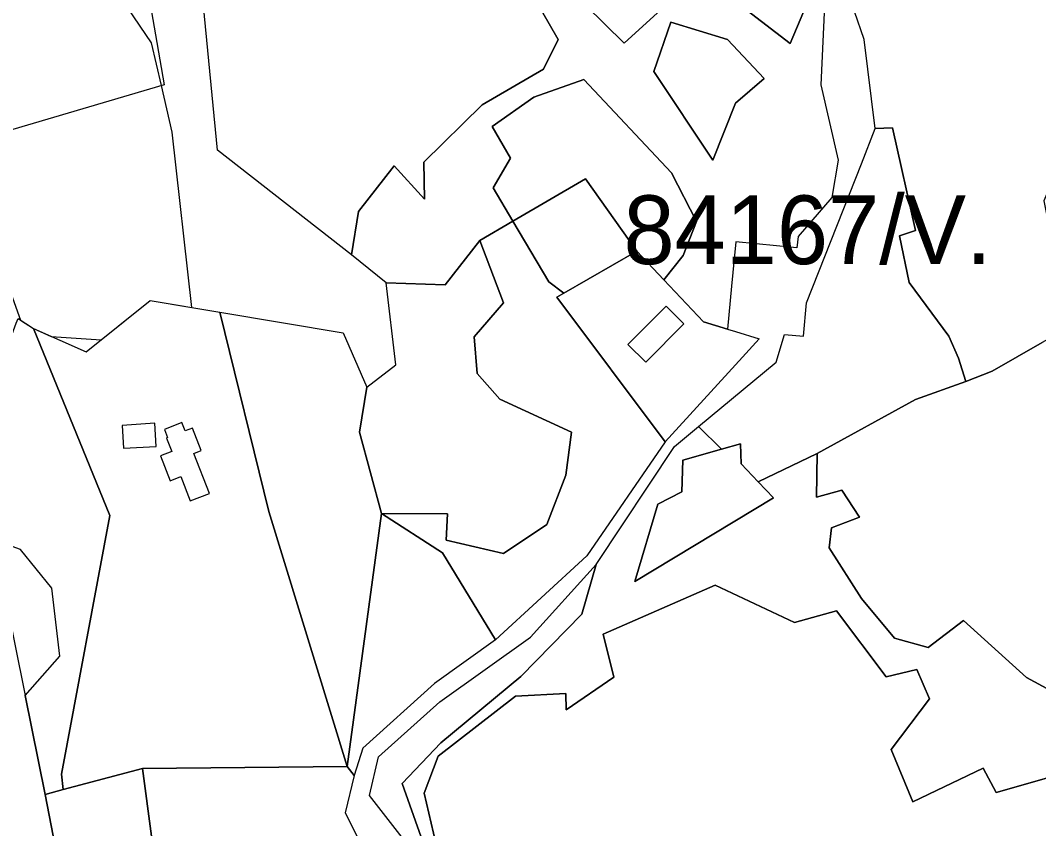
# Model space of a CAD drawing. Extents: x -477304 to -465429, y -1159113 to -1149210.
# Drawn here: x -475087.6 to -474865.5, y -1151412.5 to -1151236.1 of the extents above; entities that cross this region are included whole.
import ezdxf

# ---------------------------------------------------------------- set-up
doc = ezdxf.new("R2010")
doc.units = 0
for name, color, linetype in [('BPEJ_s', 7, 'Continuous'), ('orna_s', 7, 'Continuous'), ('PUPFL_s', 7, 'Continuous'), ('trav_porost_s', 7, 'Continuous'), ('zahrada_s', 7, 'Continuous')]:
    doc.layers.add(name, color=color, linetype=linetype)

msp = doc.modelspace()

# ---------------------------------------------------------------- linework, layer by layer
at = {"layer": 'BPEJ_s'}
msp.add_lwpolyline([(-475097.5, -1151274.05), (-475087.6, -1151301.52), (-475084.79, -1151303.35), (-475080.93, -1151305.06), (-475076.58, -1151305.36), (-475070.02, -1151305.82), (-475059.29, -1151297.19), (-475050.25, -1151298.71), (-475054.5, -1151260.5), (-475056.85, -1151250.3), (-475059, -1151241), (-475088.5, -1151197.5)], dxfattribs=at)
msp.add_lwpolyline([(-475097.5, -1151274.05), (-475087.6, -1151301.52), (-475084.79, -1151303.35), (-475080.93, -1151305.06), (-475076.58, -1151305.36), (-475070.02, -1151305.82), (-475059.29, -1151297.19), (-475050.25, -1151298.71), (-475054.5, -1151260.5), (-475056.85, -1151250.3), (-475059, -1151241), (-475088.5, -1151197.5)], dxfattribs=at)
at = {"layer": 'orna_s'}
for points in [[(-475073.3, -1151308.45), (-475059.29, -1151297.19), (-475044.09, -1151299.75), (-475033.4, -1151343.25), (-475016.37, -1151398.97), (-475060.99, -1151399.35), (-475078.27, -1151403.96), (-475078.67, -1151400.58), (-475068.11, -1151344.11), (-475084.79, -1151303.35)], [(-475065.43, -1151324.48), (-475065.15, -1151329.47), (-475058.04, -1151329.07), (-475058.32, -1151323.98)], [(-475048.2, -1151329.99), (-475050.1, -1151325.06), (-475051.69, -1151325.67), (-475052.38, -1151323.87), (-475056.21, -1151325.35), (-475055.51, -1151327.15), (-475055.74, -1151327.24), (-475054.61, -1151330.17), (-475057.04, -1151331.11), (-475054.94, -1151336.55), (-475052.63, -1151335.66), (-475050.59, -1151340.95), (-475046.41, -1151339.34), (-475049.78, -1151330.6)], [(-475060.99, -1151399.35), (-475057.18, -1151427.79), (-475077.46, -1151429.88), (-475082.26, -1151405.02), (-475078.27, -1151403.96)]]:
    msp.add_lwpolyline(points, close=True, dxfattribs=at)
at = {"layer": 'PUPFL_s'}
msp.add_lwpolyline([(-475060.36, -1151226.55), (-475056.29, -1151250.13), (-475098.2, -1151262.5)], dxfattribs=at)
at = {"layer": 'trav_porost_s'}
for points in [[(-475047.71, -1151232.87), (-475050.28, -1151227.84), (-475056.07, -1151224.83), (-475054.41, -1151208.13), (-475050, -1151194.33), (-475037.4, -1151193.53), (-475018.48, -1151195.89), (-474998.6, -1151206.44), (-474978.98, -1151225.14), (-474970.27, -1151240.23), (-474973.53, -1151246.68), (-474986.86, -1151254.47), (-474999.59, -1151267), (-474999.46, -1151275.08), (-475006.05, -1151267.82), (-475013.84, -1151277.82), (-475015.4, -1151287.21), (-475044.66, -1151264.4)], [(-474933.34, -1151240.25), (-474925.38, -1151248.72), (-474931.62, -1151254.12), (-474936.54, -1151266.6), (-474949.42, -1151247.26), (-474945.74, -1151236.46)], [(-474936.54, -1151266.6), (-474931.62, -1151254.12), (-474925.38, -1151248.72), (-474933.34, -1151240.25), (-474945.74, -1151236.46), (-474949.42, -1151247.26)], [(-474940.14, -1151279.96), (-474943.03, -1151287.39), (-474947.23, -1151292.73), (-474953.12, -1151286.46), (-474964.32, -1151270.65), (-474980.18, -1151279.87), (-474984.46, -1151272.64), (-474980.74, -1151266.12), (-474984.68, -1151259.2), (-474975.61, -1151252.8), (-474964.73, -1151249), (-474945.57, -1151269.38)], [(-474964.32, -1151270.65), (-474953.12, -1151286.46), (-474969.06, -1151295.61), (-474972.31, -1151293.16), (-474980.18, -1151279.87)], [(-474964.05, -1151352.96), (-474984.01, -1151371.26), (-474995.53, -1151352.32), (-475008.82, -1151343.69), (-474994.48, -1151343.79), (-474994.77, -1151349.54), (-474982.2, -1151352.41), (-474972.78, -1151346.11), (-474968.66, -1151335.35), (-474967.41, -1151325.96), (-474983.01, -1151318.78), (-474988, -1151313.15), (-474988.65, -1151305.18), (-474982.24, -1151297.7), (-474987.42, -1151284.08), (-474980.18, -1151279.87), (-474972.31, -1151293.16), (-474969.06, -1151295.61), (-474970.62, -1151296.51), (-474946.97, -1151328.05)], [(-474988, -1151313.15), (-474983.01, -1151318.78), (-474967.41, -1151325.96), (-474968.66, -1151335.35), (-474972.78, -1151346.11), (-474982.2, -1151352.41), (-474994.77, -1151349.54), (-474994.48, -1151343.79), (-475008.82, -1151343.69), (-475013.63, -1151325.93), (-475012.08, -1151316.13), (-475005.7, -1151311.26), (-475007.86, -1151293.38), (-474994.97, -1151293.8), (-474987.42, -1151284.08), (-474982.24, -1151297.7), (-474988.65, -1151305.18)], [(-474930.1, -1151309.59), (-474946.97, -1151328.05), (-474970.62, -1151296.51), (-474969.06, -1151295.61), (-474953.12, -1151286.46), (-474947.23, -1151292.73), (-474938.6, -1151301.9), (-474933.37, -1151303.48), (-474931.65, -1151303.97), (-474926.42, -1151305.57)], [(-475008.82, -1151343.69), (-475016.37, -1151398.97), (-475033.4, -1151343.25), (-475044.09, -1151299.75), (-475017.18, -1151304.29), (-475012.08, -1151316.13), (-475013.63, -1151325.93)], [(-474942.86, -1151302.31), (-474946.76, -1151298.43), (-474955.1, -1151306.8), (-474951.2, -1151310.68)], [(-475068.11, -1151344.11), (-475078.67, -1151400.58), (-475078.27, -1151403.96), (-475082.26, -1151405.02), (-475086.62, -1151383.42), (-475079.05, -1151374.83), (-475080.8, -1151360), (-475087.6, -1151351.55), (-475093.48, -1151349.48), (-475093.77, -1151348.04), (-475098.68, -1151329.69), (-475088.52, -1151302.19), (-475088.14, -1151301.17), (-475084.79, -1151303.35)], [(-474943.13, -1151332.06), (-474934.65, -1151329.67), (-474930.56, -1151328.52), (-474930.38, -1151332.86), (-474926.66, -1151336.77), (-474923.3, -1151340.3), (-474953.61, -1151358.53), (-474948.53, -1151341.67), (-474943.36, -1151338.98)], [(-475077.46, -1151429.88), (-475130.42, -1151438.02), (-475153.01, -1151444.89), (-475179.97, -1151451.76), (-475213.34, -1151457.24), (-475215.93, -1151423.64), (-475206.57, -1151412.14), (-475177, -1151398.54), (-475135.17, -1151384.64), (-475124.91, -1151385.36), (-475104.73, -1151378.99), (-475096.15, -1151371.76), (-475095.79, -1151365.7), (-475103.16, -1151351.41), (-475098.18, -1151340.89), (-475093.77, -1151348.04), (-475093.48, -1151349.48), (-475086.62, -1151383.42), (-475082.26, -1151405.02)], [(-475012.91, -1151394.95), (-475014.84, -1151400.93), (-475016.37, -1151398.97), (-475008.82, -1151343.69), (-474995.53, -1151352.32), (-474984.01, -1151371.26), (-474997.32, -1151380.82)], [(-475000.29, -1151419.64), (-475011.44, -1151405.3), (-475009.51, -1151396.79), (-474996.09, -1151384.8), (-474976.36, -1151370.73), (-474962, -1151354.84), (-474965.16, -1151365.68), (-474978.44, -1151379.28), (-474995.87, -1151393.75), (-475004.34, -1151402.64), (-474998.98, -1151417.87), (-474989.47, -1151430.51), (-474993.76, -1151429.67), (-474998.64, -1151426.37)], [(-475060.99, -1151399.35), (-475016.37, -1151398.97), (-475014.84, -1151400.93), (-475016.78, -1151409.02), (-475010.6, -1151421.29), (-475040.18, -1151426.03), (-475044.87, -1151426.5), (-475057.18, -1151427.79)]]:
    msp.add_lwpolyline(points, close=True, dxfattribs=at)
for points in [[(-474850.5, -1151227.4), (-474855.72, -1151237.99), (-474855.66, -1151255.2), (-474864.31, -1151275.47), (-474861.96, -1151287.59), (-474860.18, -1151294.77), (-474858.21, -1151302.73), (-474864.74, -1151306.37), (-474875.64, -1151312.66), (-474881.35, -1151314.91), (-474882.97, -1151309.77), (-474885.1, -1151304.99), (-474893.75, -1151293.3), (-474895.83, -1151283.09), (-474892.31, -1151281.94), (-474897.38, -1151259.52), (-474901.14, -1151259.66), (-474903.51, -1151240.22), (-474912, -1151215.7)], [(-474912, -1151227.99), (-474913, -1151250.17), (-474909.19, -1151266.61), (-474910.61, -1151274.72), (-474917.93, -1151283.24), (-474918.26, -1151285.7), (-474931.57, -1151284.44), (-474932.48, -1151294.08), (-474933.37, -1151303.48), (-474938.6, -1151301.9), (-474947.23, -1151292.73), (-474943.03, -1151287.39), (-474940.14, -1151279.96), (-474945.57, -1151269.38), (-474964.73, -1151249), (-474975.61, -1151252.8), (-474984.68, -1151259.2), (-474980.74, -1151266.12), (-474984.46, -1151272.64), (-474980.18, -1151279.87), (-474987.42, -1151284.08), (-474994.97, -1151293.8), (-475007.86, -1151293.38), (-475015.4, -1151287.21), (-475013.84, -1151277.82), (-475006.05, -1151267.82), (-474999.46, -1151275.08), (-474999.59, -1151267), (-474986.86, -1151254.47), (-474973.53, -1151246.68), (-474970.27, -1151240.23), (-474978.98, -1151225.14)], [(-474913.93, -1151227.46), (-474919.67, -1151241.13), (-474938.45, -1151226.62)], [(-474938.45, -1151226.62), (-474919.67, -1151241.13), (-474913.93, -1151227.46)], [(-474947.01, -1151232.94), (-474955.87, -1151241.06), (-474964.33, -1151232.75)], [(-474964.33, -1151232.75), (-474955.87, -1151241.06), (-474947.01, -1151232.94)], [(-474841.95, -1151393.7), (-474868.16, -1151379.49), (-474881.86, -1151367.04), (-474889.55, -1151372.96), (-474896.91, -1151370.95), (-474904.12, -1151362.28), (-474911.15, -1151351.21), (-474910.66, -1151346.81), (-474904.58, -1151344.53), (-474908.44, -1151338.59), (-474913.95, -1151340.17), (-474913.82, -1151330.63), (-474892.34, -1151318.82), (-474881.35, -1151314.91), (-474875.64, -1151312.66), (-474864.74, -1151306.37)], [(-474998.98, -1151417.87), (-475004.34, -1151402.64), (-474995.87, -1151393.75), (-474978.44, -1151379.28), (-474965.16, -1151365.68), (-474962, -1151354.84), (-474944.9, -1151329.06), (-474939.66, -1151324.7), (-474934.65, -1151329.67), (-474943.13, -1151332.06), (-474943.36, -1151338.98), (-474948.53, -1151341.67), (-474953.61, -1151358.53), (-474923.3, -1151340.3), (-474926.66, -1151336.77), (-474913.82, -1151330.63), (-474913.95, -1151340.17), (-474908.44, -1151338.59), (-474904.58, -1151344.53), (-474910.66, -1151346.81), (-474911.15, -1151351.21), (-474904.12, -1151362.28), (-474896.91, -1151370.95), (-474889.55, -1151372.96), (-474881.86, -1151367.04), (-474868.16, -1151379.49), (-474841.95, -1151393.7)], [(-474996.96, -1151415.64), (-474999.56, -1151404.78), (-474996.47, -1151396.66), (-474979.64, -1151383.57), (-474968.61, -1151383), (-474968.56, -1151386.6), (-474958.16, -1151379.4), (-474960.5, -1151370.08), (-474936.07, -1151359.33), (-474918.76, -1151367.51), (-474909.57, -1151364.94), (-474898.76, -1151379.37), (-474892.07, -1151377.74), (-474889.31, -1151384.2), (-474897.69, -1151395.21), (-474892.91, -1151406.62), (-474877.57, -1151399.29), (-474874.75, -1151404.62), (-474862.78, -1151401.22)], [(-474862.78, -1151401.22), (-474874.75, -1151404.62), (-474877.57, -1151399.29), (-474892.91, -1151406.62), (-474897.69, -1151395.21), (-474889.31, -1151384.2), (-474892.07, -1151377.74), (-474898.76, -1151379.37), (-474909.57, -1151364.94), (-474918.76, -1151367.51), (-474936.07, -1151359.33), (-474960.5, -1151370.08), (-474958.16, -1151379.4), (-474968.56, -1151386.6), (-474968.61, -1151383), (-474979.64, -1151383.57), (-474996.47, -1151396.66), (-474999.56, -1151404.78), (-474996.96, -1151415.64)]]:
    msp.add_lwpolyline(points, dxfattribs=at)
at = {"layer": 'zahrada_s'}
msp.add_lwpolyline([(-474897.38, -1151259.52), (-474892.31, -1151281.94), (-474895.83, -1151283.09), (-474893.75, -1151293.3), (-474885.1, -1151304.99), (-474882.97, -1151309.77), (-474881.35, -1151314.91), (-474892.34, -1151318.82), (-474913.82, -1151330.63), (-474926.66, -1151336.77), (-474930.38, -1151332.86), (-474930.56, -1151328.52), (-474934.65, -1151329.67), (-474939.66, -1151324.7), (-474922.76, -1151310.65), (-474920.91, -1151304.61), (-474916.79, -1151305), (-474916.1, -1151297.72), (-474904.1, -1151267.41), (-474901.14, -1151259.66)], close=True, dxfattribs=at)

# ---------------------------------------------------------------- texts
at = {"layer": 'BPEJ_s'}
msp.add_text('84167/V.', height=15, dxfattribs=at).set_placement((-474956.05, -1151289.28))

doc.saveas('drawing.dxf')
